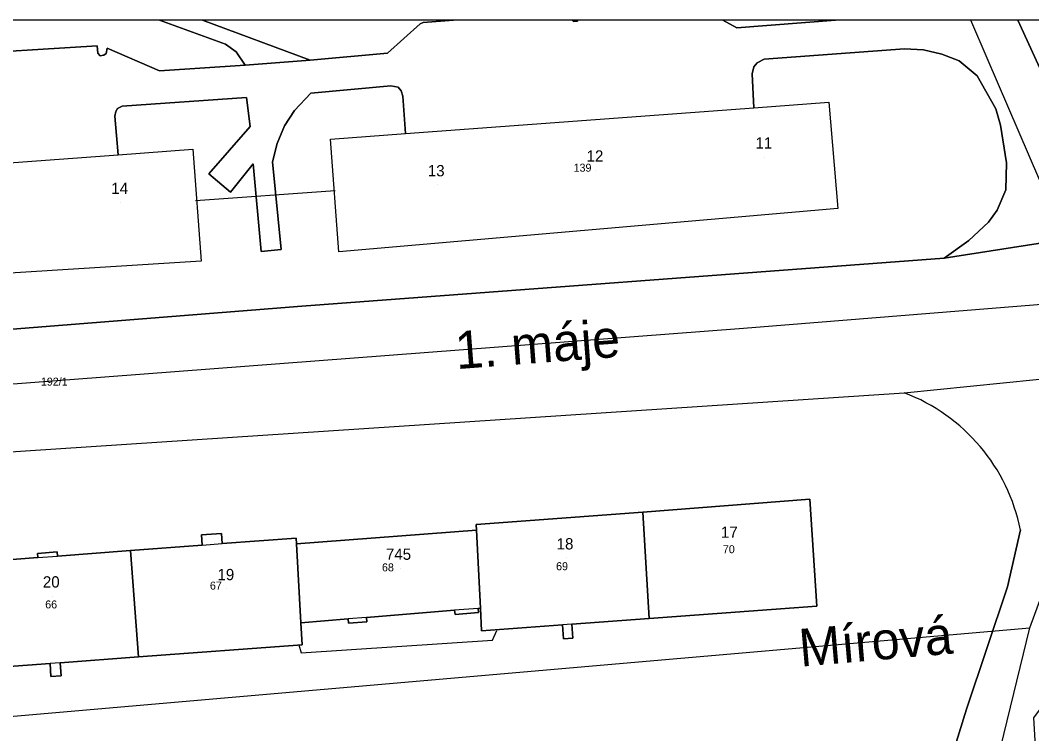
# Model space of a CAD drawing. Extents: x -873642 to -872917, y -1012962 to -1012567.
# Drawn here: x -873173.4 to -873065.9, y -1012643.4 to -1012567.5 of the extents above; entities that cross this region are included whole.
import ezdxf

# ---------------------------------------------------------------- set-up
doc = ezdxf.new("R2010")
doc.units = 0
for name, color, linetype in [('adresni_misto', 7, 'Continuous'), ('cisla_parcelni_kn', 7, 'Continuous'), ('cislo_domovni', 7, 'Continuous'), ('osy_ulic', 7, 'Continuous'), ('parcely_kn', 7, 'Continuous'), ('stavebni_objekty_bydleni', 7, 'Continuous'), ('TRASY - zamereno', 7, 'Continuous'), ('ulice', 7, 'Continuous')]:
    doc.layers.add(name, color=color, linetype=linetype)

msp = doc.modelspace()

# ---------------------------------------------------------------- linework, layer by layer
at = {"layer": 'adresni_misto'}
for p, q in [((-873094.25, -1012582.06), (-873094.25, -1012582.06)), ((-873112.19, -1012583.44), (-873112.19, -1012583.44)), ((-873129.06, -1012585), (-873129.06, -1012585)), ((-873162.69, -1012586.88), (-873162.69, -1012586.88)), ((-873097.91, -1012623.44), (-873097.91, -1012623.44)), ((-873115.37, -1012624.68), (-873115.37, -1012624.68)), ((-873132.91, -1012625.78), (-873132.91, -1012625.78)), ((-873169.96, -1012628.73), (-873169.96, -1012628.73)), ((-873151.41, -1012627.95), (-873151.41, -1012627.95))]:
    msp.add_line(p, q, dxfattribs=at)
at = {"layer": 'osy_ulic'}
for points in [[(-873059.56, -1012597.3), (-873070.62, -1012571.55), (-873072.35, -1012567.5)], [(-872916.93, -1012586.66), (-872957.62, -1012590.24), (-872977.73, -1012591.46), (-872994.83, -1012592.51), (-873031.96, -1012595.34), (-873059.56, -1012597.3), (-873096.52, -1012600.28), (-873281.07, -1012614.36), (-873481.95, -1012629.68)], [(-873411.85, -1012822.53), (-873317.85, -1012788.44), (-873277.23, -1012773.91), (-873252.76, -1012767.01), (-873201.18, -1012755.57), (-873115.6, -1012739.3), (-873104.65, -1012731.3), (-873088.93, -1012706.26), (-873080.41, -1012681.66), (-873071.61, -1012653.78), (-873070.57, -1012650.45), (-873066.08, -1012632.13), (-873063.74, -1012625.63), (-873059.56, -1012597.3)], [(-873478.28, -1012662.13), (-873469.53, -1012661.58), (-873334.68, -1012652.02), (-873276.17, -1012648.25), (-873178.17, -1012641.86), (-873066.08, -1012632.13)]]:
    msp.add_lwpolyline(points, dxfattribs=at)
at = {"layer": 'parcely_kn'}
for p, q in [((-873158.58, -1012567.5), (-873319.68, -1012567.5)), ((-873158.58, -1012567.5), (-873319.68, -1012567.5)), ((-873154.01, -1012567.5), (-873158.58, -1012567.5)), ((-873154.01, -1012567.5), (-873158.58, -1012567.5)), ((-873127.32, -1012567.5), (-873154.01, -1012567.5)), ((-873127.32, -1012567.5), (-873154.01, -1012567.5)), ((-873114.72, -1012567.5), (-873127.32, -1012567.5)), ((-873114.72, -1012567.5), (-873127.32, -1012567.5)), ((-873114.11, -1012567.5), (-873114.72, -1012567.5)), ((-873114.11, -1012567.5), (-873114.72, -1012567.5)), ((-873098.71, -1012567.5), (-873114.11, -1012567.5)), ((-873098.71, -1012567.5), (-873114.11, -1012567.5)), ((-873086.75, -1012567.5), (-873098.71, -1012567.5)), ((-873086.75, -1012567.5), (-873098.71, -1012567.5)), ((-873067.36, -1012567.5), (-873086.75, -1012567.5)), ((-873067.36, -1012567.5), (-873086.75, -1012567.5)), ((-873038.24, -1012567.5), (-873067.36, -1012567.5)), ((-873038.24, -1012567.5), (-873067.36, -1012567.5))]:
    msp.add_line(p, q, dxfattribs=at)
for points in [[(-873127.32, -1012567.5), (-873130.54, -1012567.74), (-873130.88, -1012567.88), (-873134.35, -1012571.02), (-873142.55, -1012571.76), (-873149.45, -1012572.28), (-873158.57, -1012572.88), (-873164.12, -1012570.46), (-873164.24, -1012571.03), (-873164.48, -1012571.23), (-873164.86, -1012571.29), (-873165.13, -1012571.01), (-873165.19, -1012570.24), (-873181.27, -1012571.22)], [(-873181.27, -1012571.22), (-873165.19, -1012570.24), (-873165.13, -1012571.01), (-873164.86, -1012571.29), (-873164.48, -1012571.23), (-873164.24, -1012571.03), (-873164.12, -1012570.46), (-873158.57, -1012572.88), (-873149.45, -1012572.28), (-873150.43, -1012570.86), (-873151.57, -1012570.06), (-873158.58, -1012567.5)], [(-873127.32, -1012567.5), (-873130.54, -1012567.74), (-873130.88, -1012567.88), (-873134.35, -1012571.02), (-873142.55, -1012571.76), (-873149.45, -1012572.28), (-873158.57, -1012572.88), (-873164.12, -1012570.46), (-873164.24, -1012571.03), (-873164.48, -1012571.23), (-873164.86, -1012571.29), (-873165.13, -1012571.01), (-873165.19, -1012570.24), (-873181.27, -1012571.22)], [(-873181.27, -1012571.22), (-873165.19, -1012570.24), (-873165.13, -1012571.01), (-873164.86, -1012571.29), (-873164.48, -1012571.23), (-873164.24, -1012571.03), (-873164.12, -1012570.46), (-873158.57, -1012572.88), (-873149.45, -1012572.28), (-873150.43, -1012570.86), (-873151.57, -1012570.06), (-873158.58, -1012567.5)], [(-873158.58, -1012567.5), (-873151.57, -1012570.06), (-873150.43, -1012570.86), (-873149.45, -1012572.28), (-873142.55, -1012571.76), (-873154.01, -1012567.5)], [(-873158.58, -1012567.5), (-873151.57, -1012570.06), (-873150.43, -1012570.86), (-873149.45, -1012572.28), (-873142.55, -1012571.76), (-873154.01, -1012567.5)], [(-873154.01, -1012567.5), (-873142.55, -1012571.76), (-873134.35, -1012571.02), (-873130.88, -1012567.88), (-873130.54, -1012567.74), (-873127.32, -1012567.5)], [(-873154.01, -1012567.5), (-873142.55, -1012571.76), (-873134.35, -1012571.02), (-873130.88, -1012567.88), (-873130.54, -1012567.74), (-873127.32, -1012567.5)], [(-873114.11, -1012567.5), (-873114.19, -1012567.59), (-873114.58, -1012567.62), (-873114.72, -1012567.5)], [(-873114.72, -1012567.5), (-873114.58, -1012567.62), (-873114.19, -1012567.59), (-873114.11, -1012567.5)], [(-873114.11, -1012567.5), (-873114.19, -1012567.59), (-873114.58, -1012567.62), (-873114.72, -1012567.5)], [(-873114.72, -1012567.5), (-873114.58, -1012567.62), (-873114.19, -1012567.59), (-873114.11, -1012567.5)], [(-873086.75, -1012567.5), (-873097.23, -1012568.31), (-873098.71, -1012567.5)], [(-873098.71, -1012567.5), (-873097.23, -1012568.31), (-873086.75, -1012567.5)], [(-873086.75, -1012567.5), (-873097.23, -1012568.31), (-873098.71, -1012567.5)], [(-873098.71, -1012567.5), (-873097.23, -1012568.31), (-873086.75, -1012567.5)], [(-873060.9, -1012581.64), (-873067.36, -1012567.5)], [(-873067.36, -1012567.5), (-873060.9, -1012581.64), (-873059.64, -1012583.92), (-873057.64, -1012586.57), (-873054.1, -1012589.49), (-873024.38, -1012587.43), (-873023.12, -1012582.82), (-873018.76, -1012567.5)], [(-873060.9, -1012581.64), (-873067.36, -1012567.5)], [(-873067.36, -1012567.5), (-873060.9, -1012581.64), (-873059.64, -1012583.92), (-873057.64, -1012586.57), (-873054.1, -1012589.49), (-873024.38, -1012587.43), (-873023.12, -1012582.82), (-873018.76, -1012567.5)], [(-873216.55, -1012603.73), (-873143.44, -1012597.91), (-873075.21, -1012592.8), (-873072.57, -1012590.91), (-873070.49, -1012588.99), (-873069.55, -1012587.7), (-873068.66, -1012585.52), (-873068.57, -1012582.67), (-873069.22, -1012578.65), (-873069.7, -1012576.93), (-873071.7, -1012573.42), (-873073.6, -1012571.81), (-873075.44, -1012571.1), (-873077.41, -1012570.66), (-873079.42, -1012570.55), (-873094.32, -1012571.63), (-873095.08, -1012572.02), (-873095.42, -1012572.47), (-873095.59, -1012573.2), (-873095.42, -1012576.8), (-873087.46, -1012576.21), (-873086.48, -1012587.53), (-873139.52, -1012592.12), (-873140.41, -1012580.14), (-873132.44, -1012579.55), (-873132.73, -1012575.56), (-873132.89, -1012575), (-873133.21, -1012574.62), (-873133.98, -1012574.49), (-873142.48, -1012575.24), (-873144.21, -1012577.09), (-873145.3, -1012578.74), (-873146.08, -1012580.61), (-873146.56, -1012582.55), (-873145.65, -1012591.88), (-873147.77, -1012592.11), (-873148.61, -1012582.76), (-873151.04, -1012585.78), (-873153.31, -1012583.85), (-873148.93, -1012578.79), (-873149.34, -1012575.72), (-873162.55, -1012576.63), (-873163.04, -1012576.89), (-873163.21, -1012577.21), (-873163.32, -1012577.69), (-873162.95, -1012581.8), (-873155.02, -1012581.21), (-873154.13, -1012593.11), (-873207.27, -1012596.44)], [(-873216.55, -1012603.73), (-873143.44, -1012597.91), (-873075.21, -1012592.8), (-873072.57, -1012590.91), (-873070.49, -1012588.99), (-873069.55, -1012587.7), (-873068.66, -1012585.52), (-873068.57, -1012582.67), (-873069.22, -1012578.65), (-873069.7, -1012576.93), (-873071.7, -1012573.42), (-873073.6, -1012571.81), (-873075.44, -1012571.1), (-873077.41, -1012570.66), (-873079.42, -1012570.55), (-873094.32, -1012571.63), (-873095.08, -1012572.02), (-873095.42, -1012572.47), (-873095.59, -1012573.2), (-873095.42, -1012576.8), (-873087.46, -1012576.21), (-873086.48, -1012587.53), (-873139.52, -1012592.12), (-873140.41, -1012580.14), (-873132.44, -1012579.55), (-873132.73, -1012575.56), (-873132.89, -1012575), (-873133.21, -1012574.62), (-873133.98, -1012574.49), (-873142.48, -1012575.24), (-873144.21, -1012577.09), (-873145.3, -1012578.74), (-873146.08, -1012580.61), (-873146.56, -1012582.55), (-873145.65, -1012591.88), (-873147.77, -1012592.11), (-873148.61, -1012582.76), (-873151.04, -1012585.78), (-873153.31, -1012583.85), (-873148.93, -1012578.79), (-873149.34, -1012575.72), (-873162.55, -1012576.63), (-873163.04, -1012576.89), (-873163.21, -1012577.21), (-873163.32, -1012577.69), (-873162.95, -1012581.8), (-873155.02, -1012581.21), (-873154.13, -1012593.11), (-873207.27, -1012596.44)], [(-873200.1, -1012584.54), (-873162.95, -1012581.8), (-873163.32, -1012577.69), (-873163.21, -1012577.21), (-873163.04, -1012576.89), (-873162.55, -1012576.63), (-873149.34, -1012575.72), (-873148.93, -1012578.79), (-873153.31, -1012583.85), (-873151.04, -1012585.78), (-873148.61, -1012582.76), (-873147.77, -1012592.11), (-873145.65, -1012591.88), (-873146.56, -1012582.55), (-873146.08, -1012580.61), (-873145.3, -1012578.74), (-873144.21, -1012577.09), (-873142.48, -1012575.24), (-873133.98, -1012574.49), (-873133.21, -1012574.62), (-873132.89, -1012575), (-873132.73, -1012575.56), (-873132.44, -1012579.55), (-873095.42, -1012576.8), (-873095.59, -1012573.2), (-873095.42, -1012572.47), (-873095.08, -1012572.02), (-873094.32, -1012571.63), (-873079.42, -1012570.55), (-873077.41, -1012570.66), (-873075.44, -1012571.1), (-873073.6, -1012571.81), (-873071.7, -1012573.42), (-873069.7, -1012576.93), (-873069.22, -1012578.65), (-873068.57, -1012582.67), (-873068.66, -1012585.52), (-873069.55, -1012587.7), (-873070.49, -1012588.99), (-873072.57, -1012590.91), (-873075.21, -1012592.8), (-873054.1, -1012589.49)], [(-873200.1, -1012584.54), (-873162.95, -1012581.8), (-873163.32, -1012577.69), (-873163.21, -1012577.21), (-873163.04, -1012576.89), (-873162.55, -1012576.63), (-873149.34, -1012575.72), (-873148.93, -1012578.79), (-873153.31, -1012583.85), (-873151.04, -1012585.78), (-873148.61, -1012582.76), (-873147.77, -1012592.11), (-873145.65, -1012591.88), (-873146.56, -1012582.55), (-873146.08, -1012580.61), (-873145.3, -1012578.74), (-873144.21, -1012577.09), (-873142.48, -1012575.24), (-873133.98, -1012574.49), (-873133.21, -1012574.62), (-873132.89, -1012575), (-873132.73, -1012575.56), (-873132.44, -1012579.55), (-873095.42, -1012576.8), (-873095.59, -1012573.2), (-873095.42, -1012572.47), (-873095.08, -1012572.02), (-873094.32, -1012571.63), (-873079.42, -1012570.55), (-873077.41, -1012570.66), (-873075.44, -1012571.1), (-873073.6, -1012571.81), (-873071.7, -1012573.42), (-873069.7, -1012576.93), (-873069.22, -1012578.65), (-873068.57, -1012582.67), (-873068.66, -1012585.52), (-873069.55, -1012587.7), (-873070.49, -1012588.99), (-873072.57, -1012590.91), (-873075.21, -1012592.8), (-873054.1, -1012589.49)], [(-872916.93, -1012583.06), (-872931.53, -1012584.18), (-872955.82, -1012586.14), (-872974.01, -1012587.35), (-872995.95, -1012588.42), (-873022.23, -1012590.98), (-873043.04, -1012592.4), (-873047.29, -1012592.28), (-873050.36, -1012591.35), (-873054.1, -1012589.49), (-873075.21, -1012592.8), (-873143.44, -1012597.91), (-873216.55, -1012603.73)], [(-873273.72, -1012619.94), (-873079.43, -1012607.12), (-873054.9, -1012604.66), (-873052.37, -1012604.41), (-873050.31, -1012602.24), (-873047.57, -1012601.38), (-872987.5, -1012597.44), (-872986.52, -1012596.03), (-872985.48, -1012595.15), (-872984.31, -1012594.39), (-872970.43, -1012593.36), (-872967.88, -1012593.04), (-872950.87, -1012593.5), (-872930.93, -1012593.98), (-872925.9, -1012594.03), (-872921.95, -1012593.97), (-872917.07, -1012593.66), (-872916.93, -1012593.65)], [(-873079.43, -1012607.12), (-873054.9, -1012604.66), (-873052.37, -1012604.41), (-873054.28, -1012608.24), (-873059.76, -1012619.22), (-873058.34, -1012622.19), (-873062.75, -1012637.7), (-873065.7, -1012641.7), (-873065.38, -1012647.07), (-873066.31, -1012649.31), (-873079.09, -1012694.9), (-873083.74, -1012706.73), (-873087.64, -1012713.81), (-873091.65, -1012719.56), (-873097.47, -1012726.79), (-873099.7, -1012729.49), (-873101.03, -1012731.11), (-873105.65, -1012736.17), (-873110.07, -1012739.5), (-873114.5, -1012741.96), (-873122.26, -1012744.11), (-873135.01, -1012746.72), (-873148.18, -1012749.22), (-873185.58, -1012756.25)], [(-873079.43, -1012607.12), (-873054.9, -1012604.66), (-873052.37, -1012604.41), (-873054.28, -1012608.24), (-873059.76, -1012619.22), (-873058.34, -1012622.19), (-873062.75, -1012637.7), (-873065.7, -1012641.7), (-873065.38, -1012647.07), (-873066.31, -1012649.31), (-873079.09, -1012694.9), (-873083.74, -1012706.73), (-873087.64, -1012713.81), (-873091.65, -1012719.56), (-873097.47, -1012726.79), (-873099.7, -1012729.49), (-873101.03, -1012731.11), (-873105.65, -1012736.17), (-873110.07, -1012739.5), (-873114.5, -1012741.96), (-873122.26, -1012744.11), (-873135.01, -1012746.72), (-873148.18, -1012749.22), (-873185.58, -1012756.25)], [(-873407.08, -1012629.93), (-873286.69, -1012620.81), (-873282.45, -1012620.53), (-873276.73, -1012620.14), (-873273.72, -1012619.94), (-873079.43, -1012607.12)], [(-873407.08, -1012629.93), (-873286.69, -1012620.81), (-873282.45, -1012620.53), (-873276.73, -1012620.14), (-873273.72, -1012619.94), (-873079.43, -1012607.12)], [(-873178.41, -1012636.51), (-873170.2, -1012635.91), (-873170.1, -1012637.3), (-873169.03, -1012637.22), (-873169.13, -1012635.82), (-873160.8, -1012635.21), (-873143.41, -1012633.92), (-873143.54, -1012631.57), (-873138.51, -1012631.16), (-873138.47, -1012631.61), (-873136.53, -1012631.46), (-873136.57, -1012631.01), (-873127.21, -1012630.25), (-873127.17, -1012630.7), (-873124.68, -1012630.5), (-873124.72, -1012630.05), (-873124.47, -1012630.03), (-873124.35, -1012632.43), (-873115.75, -1012631.8), (-873115.64, -1012633.3), (-873114.64, -1012633.22), (-873114.75, -1012631.72), (-873106.55, -1012631.12), (-873088.71, -1012629.81), (-873089.47, -1012618.43), (-873107.22, -1012619.83), (-873124.93, -1012621.13), (-873124.9, -1012621.73), (-873144.01, -1012623.17), (-873144.04, -1012622.57), (-873151.9, -1012623.16), (-873151.98, -1012622.07), (-873154.12, -1012622.23), (-873154.04, -1012623.33), (-873161.65, -1012623.9), (-873169.41, -1012624.49), (-873169.44, -1012624.04), (-873171.53, -1012624.2), (-873171.5, -1012624.65), (-873179.26, -1012625.23)], [(-873178.41, -1012636.51), (-873170.2, -1012635.91), (-873170.1, -1012637.3), (-873169.03, -1012637.22), (-873169.13, -1012635.82), (-873160.8, -1012635.21), (-873143.41, -1012633.92), (-873143.54, -1012631.57), (-873138.51, -1012631.16), (-873138.47, -1012631.61), (-873136.53, -1012631.46), (-873136.57, -1012631.01), (-873127.21, -1012630.25), (-873127.17, -1012630.7), (-873124.68, -1012630.5), (-873124.72, -1012630.05), (-873124.47, -1012630.03), (-873124.35, -1012632.43), (-873115.75, -1012631.8), (-873115.64, -1012633.3), (-873114.64, -1012633.22), (-873114.75, -1012631.72), (-873106.55, -1012631.12), (-873088.71, -1012629.81), (-873089.47, -1012618.43), (-873107.22, -1012619.83), (-873124.93, -1012621.13), (-873124.9, -1012621.73), (-873144.01, -1012623.17), (-873144.04, -1012622.57), (-873151.9, -1012623.16), (-873151.98, -1012622.07), (-873154.12, -1012622.23), (-873154.04, -1012623.33), (-873161.65, -1012623.9), (-873169.41, -1012624.49), (-873169.44, -1012624.04), (-873171.53, -1012624.2), (-873171.5, -1012624.65), (-873179.26, -1012625.23)], [(-873320.46, -1012784.28), (-873268.07, -1012767.54), (-873249.92, -1012762.57), (-873226.73, -1012756.94), (-873186.64, -1012748.89), (-873149.68, -1012742.06), (-873135.84, -1012739.52), (-873124.72, -1012736.51), (-873113.32, -1012731.6), (-873103.81, -1012724.84), (-873095.71, -1012715.02), (-873089.72, -1012704.46), (-873086.77, -1012695.86), (-873085.73, -1012692.85), (-873081.52, -1012670.94), (-873077.58, -1012656.47), (-873075.63, -1012649.79), (-873072.81, -1012640.75), (-873068.46, -1012627.76), (-873067.09, -1012621.71)], [(-873320.46, -1012784.28), (-873268.07, -1012767.54), (-873249.92, -1012762.57), (-873226.73, -1012756.94), (-873186.64, -1012748.89), (-873149.68, -1012742.06), (-873135.84, -1012739.52), (-873124.72, -1012736.51), (-873113.32, -1012731.6), (-873103.81, -1012724.84), (-873095.71, -1012715.02), (-873089.72, -1012704.46), (-873086.77, -1012695.86), (-873085.73, -1012692.85), (-873081.52, -1012670.94), (-873077.58, -1012656.47), (-873075.63, -1012649.79), (-873072.81, -1012640.75), (-873068.46, -1012627.76), (-873067.09, -1012621.71)], [(-873067.09, -1012621.71), (-873068.46, -1012627.76), (-873072.81, -1012640.75), (-873075.63, -1012649.79), (-873077.58, -1012656.47), (-873081.52, -1012670.94), (-873084.44, -1012674.48), (-873086.98, -1012676.69), (-873090.68, -1012677.91), (-873095.85, -1012678.72), (-873263.61, -1012691.39)], [(-873067.09, -1012621.71), (-873068.46, -1012627.76), (-873072.81, -1012640.75), (-873075.63, -1012649.79), (-873077.58, -1012656.47), (-873081.52, -1012670.94), (-873084.44, -1012674.48), (-873086.98, -1012676.69), (-873090.68, -1012677.91), (-873095.85, -1012678.72), (-873263.61, -1012691.39)]]:
    msp.add_lwpolyline(points, dxfattribs=at)
for points in [[(-873087.46, -1012576.21), (-873086.48, -1012587.53), (-873139.52, -1012592.12), (-873140.41, -1012580.14), (-873132.44, -1012579.55), (-873095.42, -1012576.8)], [(-873087.46, -1012576.21), (-873086.48, -1012587.53), (-873139.52, -1012592.12), (-873140.41, -1012580.14), (-873132.44, -1012579.55), (-873095.42, -1012576.8)], [(-873155.02, -1012581.21), (-873154.13, -1012593.11), (-873207.27, -1012596.44), (-873207.98, -1012585.12), (-873200.1, -1012584.54), (-873162.95, -1012581.8)], [(-873155.02, -1012581.21), (-873154.13, -1012593.11), (-873207.27, -1012596.44), (-873207.98, -1012585.12), (-873200.1, -1012584.54), (-873162.95, -1012581.8)], [(-873089.47, -1012618.43), (-873088.71, -1012629.81), (-873106.55, -1012631.12), (-873107.22, -1012619.83)], [(-873089.47, -1012618.43), (-873088.71, -1012629.81), (-873106.55, -1012631.12), (-873107.22, -1012619.83)], [(-873124.93, -1012621.13), (-873107.22, -1012619.83), (-873106.55, -1012631.12), (-873114.75, -1012631.72), (-873114.64, -1012633.22), (-873115.64, -1012633.3), (-873115.75, -1012631.8), (-873124.35, -1012632.43), (-873124.47, -1012630.03), (-873124.9, -1012621.73)], [(-873124.93, -1012621.13), (-873107.22, -1012619.83), (-873106.55, -1012631.12), (-873114.75, -1012631.72), (-873114.64, -1012633.22), (-873115.64, -1012633.3), (-873115.75, -1012631.8), (-873124.35, -1012632.43), (-873124.47, -1012630.03), (-873124.9, -1012621.73)], [(-873144.04, -1012622.57), (-873144.01, -1012623.17), (-873143.54, -1012631.57), (-873143.41, -1012633.92), (-873160.8, -1012635.21), (-873161.65, -1012623.9), (-873154.04, -1012623.33), (-873154.12, -1012622.23), (-873151.98, -1012622.07), (-873151.9, -1012623.16)], [(-873144.04, -1012622.57), (-873144.01, -1012623.17), (-873143.54, -1012631.57), (-873143.41, -1012633.92), (-873160.8, -1012635.21), (-873161.65, -1012623.9), (-873154.04, -1012623.33), (-873154.12, -1012622.23), (-873151.98, -1012622.07), (-873151.9, -1012623.16)], [(-873124.47, -1012630.03), (-873124.72, -1012630.05), (-873124.68, -1012630.5), (-873127.17, -1012630.7), (-873127.21, -1012630.25), (-873136.57, -1012631.01), (-873136.53, -1012631.46), (-873138.47, -1012631.61), (-873138.51, -1012631.16), (-873143.54, -1012631.57), (-873144.01, -1012623.17), (-873124.9, -1012621.73)], [(-873124.47, -1012630.03), (-873124.72, -1012630.05), (-873124.68, -1012630.5), (-873127.17, -1012630.7), (-873127.21, -1012630.25), (-873136.57, -1012631.01), (-873136.53, -1012631.46), (-873138.47, -1012631.61), (-873138.51, -1012631.16), (-873143.54, -1012631.57), (-873144.01, -1012623.17), (-873124.9, -1012621.73)], [(-873169.13, -1012635.82), (-873169.03, -1012637.22), (-873170.1, -1012637.3), (-873170.2, -1012635.91), (-873178.41, -1012636.51), (-873179.26, -1012625.23), (-873171.5, -1012624.65), (-873171.53, -1012624.2), (-873169.44, -1012624.04), (-873169.41, -1012624.49), (-873161.65, -1012623.9), (-873160.8, -1012635.21)], [(-873169.13, -1012635.82), (-873169.03, -1012637.22), (-873170.1, -1012637.3), (-873170.2, -1012635.91), (-873178.41, -1012636.51), (-873179.26, -1012625.23), (-873171.5, -1012624.65), (-873171.53, -1012624.2), (-873169.44, -1012624.04), (-873169.41, -1012624.49), (-873161.65, -1012623.9), (-873160.8, -1012635.21)]]:
    msp.add_lwpolyline(points, close=True, dxfattribs=at)
msp.add_arc((-873086.46, -1012625.58), 19.75, 11.2938, 69.1543, dxfattribs=at)
msp.add_arc((-873086.46, -1012625.58), 19.75, 11.2938, 69.1543, dxfattribs=at)
msp.add_arc((-873086.46, -1012625.58), 19.75, 11.2938, 69.1543, dxfattribs=at)
msp.add_arc((-873086.46, -1012625.58), 19.75, 11.2938, 69.1543, dxfattribs=at)
at = {"layer": 'stavebni_objekty_bydleni'}
for points in [[(-873139.52, -1012592.12), (-873140.41, -1012580.14), (-873132.44, -1012579.55), (-873095.42, -1012576.8), (-873087.46, -1012576.21), (-873086.48, -1012587.53)], [(-873154.13, -1012593.11), (-873207.27, -1012596.44), (-873207.98, -1012585.12), (-873200.1, -1012584.54), (-873162.95, -1012581.8), (-873155.02, -1012581.21)], [(-873089.47, -1012618.43), (-873088.71, -1012629.81), (-873106.55, -1012631.12), (-873107.22, -1012619.83)], [(-873124.35, -1012632.43), (-873124.47, -1012630.03), (-873124.9, -1012621.73), (-873124.93, -1012621.13), (-873107.22, -1012619.83), (-873106.55, -1012631.12), (-873114.75, -1012631.72), (-873115.75, -1012631.8)], [(-873143.54, -1012631.57), (-873144.01, -1012623.17), (-873124.9, -1012621.73), (-873124.47, -1012630.03), (-873124.72, -1012630.05), (-873127.21, -1012630.25), (-873136.57, -1012631.01), (-873138.51, -1012631.16)], [(-873154.04, -1012623.33), (-873151.9, -1012623.16), (-873144.04, -1012622.57), (-873144.01, -1012623.17), (-873143.54, -1012631.57), (-873143.41, -1012633.92), (-873160.8, -1012635.21), (-873161.65, -1012623.9)], [(-873161.65, -1012623.9), (-873160.8, -1012635.21), (-873169.13, -1012635.82), (-873170.2, -1012635.91), (-873178.41, -1012636.51), (-873179.26, -1012625.23), (-873171.5, -1012624.65), (-873169.41, -1012624.49)]]:
    msp.add_lwpolyline(points, close=True, dxfattribs=at)
at = {"layer": 'TRASY - zamereno'}
for p, q in [((-873154.74, -1012586.67), (-873139.92, -1012585.61)), ((-873123.2, -1012633.44), (-873122.72, -1012632.4)), ((-873143.78, -1012633.94), (-873143.5, -1012634.78)), ((-873143.5, -1012634.78), (-873123.2, -1012633.44))]:
    msp.add_line(p, q, dxfattribs=at)

# ---------------------------------------------------------------- texts
at = {"layer": 'cisla_parcelni_kn'}
for s, p in [('139', (-873114.57, -1012583.61)), ('139', (-873114.57, -1012583.61)), ('192/1', (-873171.17, -1012606.36)), ('192/1', (-873171.17, -1012606.36)), ('70', (-873098.71, -1012624.18)), ('70', (-873098.71, -1012624.18)), ('68', (-873134.93, -1012626.11)), ('68', (-873134.93, -1012626.11)), ('69', (-873116.43, -1012625.99)), ('69', (-873116.43, -1012625.99)), ('67', (-873153.21, -1012628.05)), ('67', (-873153.21, -1012628.05)), ('66', (-873170.71, -1012630.05)), ('66', (-873170.71, -1012630.05))]:
    msp.add_text(s, height=0.85, dxfattribs=at).set_placement(p)
at = {"layer": 'cislo_domovni'}
for s, p in [('11', (-873095.25, -1012581.16)), ('12', (-873113.19, -1012582.54)), ('13', (-873130.06, -1012584.1)), ('14', (-873163.69, -1012585.98)), ('17', (-873098.91, -1012622.54)), ('18', (-873116.37, -1012623.78)), ('745', (-873134.51, -1012624.88)), ('20', (-873170.96, -1012627.83)), ('19', (-873152.41, -1012627.05))]:
    msp.add_text(s, height=1.2, dxfattribs=at).set_placement(p)
at = {"layer": 'ulice'}
for s, rotation, p in [('1. máje', 4.3629, (-873127, -1012604.61)), ('Mírová', 4.9611, (-873090.45, -1012636.25))]:
    msp.add_text(s, height=4, rotation=rotation, dxfattribs=at).set_placement(p)

doc.saveas('drawing.dxf')
